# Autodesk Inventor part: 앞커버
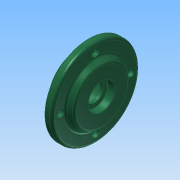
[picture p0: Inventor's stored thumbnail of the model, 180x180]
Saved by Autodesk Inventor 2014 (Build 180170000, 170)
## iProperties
Created: 2015-11
Part Number: 앞커버
Material: 알루미늄 6061
Document SubType Name: Modeling
Designer: mduedu
Density: 2.71 g/cm^3
Appearance: 매끄러움 - 짙은 바다 녹색
Mass: 290.026 g
Surface Area: 234.647 cm^2
Volume: 107.021 cm^3
Author: mduedu
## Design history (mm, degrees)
sketch "스케치1"
  geometry: C1 r 50 at (0, 0); 1 further point
  constraints: 1 centre point, 1 coincident
  dimensions: "d57" = 100 diameter of C1
extrude "돌출1" new body sketch "스케치1" distance "d3" = 8; taper "d4" = 0 deg
sketch "스케치2"
  geometry: C1 r 35 at (0, 0); 1 further point
  constraints: 1 centre point, 1 coincident
  dimensions: "d5" = 70 diameter of C1
extrude "돌출2" join sketch "스케치2" distance "d6" = 7; taper "d7" = -30 deg
sketch "스케치3" dims "d58" = 80
  geometry: 3 further points
  constraints: 2 vertical alignment, 1 coincident, 2 other
hole "구멍1" sketch "스케치3" at (0, 40) diameter "d11" = 4.5; stored, may be unused: countersink angle "d15" = 90 deg, drill point angle "d17" = 118 deg; dims "d12" = 6, "d13" = 8, "d14" = 4.4, "d16" = 8
sketch "스케치4"
  geometry: C1 r 35 at (0, 0); 1 further point
  constraints: 1 centre point, 1 coincident
  dimensions: "d21" = 70 diameter of C1
extrude "돌출3" join sketch "스케치4" distance "d23" = 12; taper "d24" = 0 deg
hole "구멍2" diameter "d27" = 30; stored, may be unused: countersink angle "d31" = 90 deg, drill point angle "d33" = 0 deg; dims "d25" = 10, "d26" = 10, "d28" = 6, "d29" = 40, "d30" = 12, "d32" = 15
fillet "모깎기3" dims "d36" = 3
fillet "모깎기4" dims "d37" = 3
fillet "모깎기5" dims "d38" = 0.3
chamfer "모따기1" distance "d39" = 1; stored, may be unused: second distance "d40" = 2, angle "d41" = 45 deg
hole "구멍3" diameter "d44" = 20; stored, may be unused: countersink angle "d48" = 90 deg, drill point angle "d50" = 118 deg; dims "d45" = 6, "d46" = 30, "d47" = 8.3, "d49" = 8, "d59" = 10, "d60" = 10
fillet "모깎기6" dims "d51" = 0.3
chamfer "모따기2" distance "d52" = 0.8; stored, may be unused: second distance "d53" = 2, angle "d54" = 30 deg
node "솔리드1"
pattern_circular "원형 패턴1" dims angle "d19" = 360 deg
